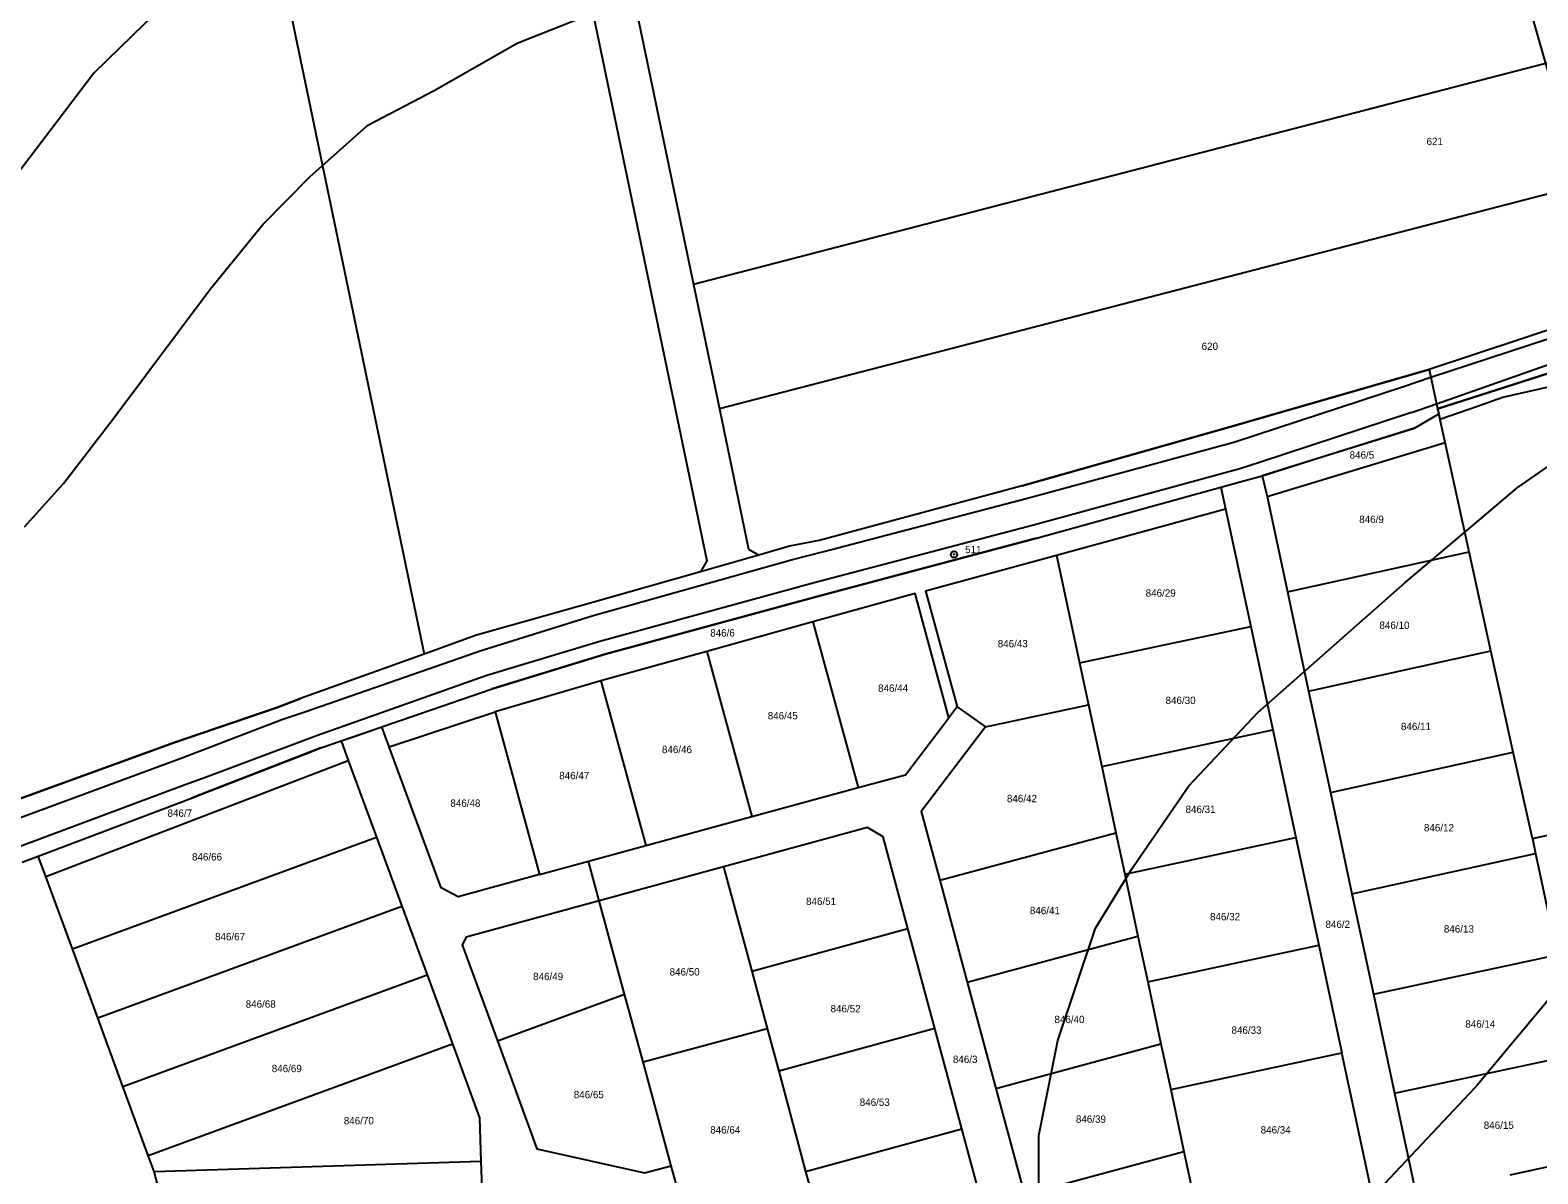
# Model space of a CAD drawing. Extents: x -725765 to -723182, y -1052705 to -1049154.
# Drawn here: x -725335 to -724986, y -1051345.9 to -1051081 of the extents above; entities that cross this region are included whole.
import ezdxf

# ---------------------------------------------------------------- set-up
doc = ezdxf.new("R2010")
doc.units = 0
for name, color, linetype in [('Vrstva 1', 7, 'Continuous'), ('Vrstva 12', 7, 'Continuous'), ('Vrstva 17', 7, 'Continuous'), ('Vrstva 18', 7, 'Continuous'), ('Vrstva 25', 7, 'Continuous'), ('Vrstva 4', 7, 'Continuous'), ('Vrstva 52', 7, 'Continuous')]:
    doc.layers.add(name, color=color, linetype=linetype)

msp = doc.modelspace()

# ---------------------------------------------------------------- linework, layer by layer
at = {"layer": 'Vrstva 1'}
for points in [[(-725237.59, -1050919.2), (-725178.34, -1051203.94)], [(-725299.6, -1050957.39), (-725243.81, -1051225.51)], [(-725199.88, -1051051.31), (-725181.44, -1051139.93)], [(-724957.95, -1051081.99), (-725181.44, -1051139.93)], [(-724945.68, -1051109.11), (-725175.46, -1051168.68)], [(-724936.98, -1051135.08), (-725011.19, -1051159.63)], [(-725181.44, -1051139.93), (-725175.46, -1051168.68)], [(-725057.43, -1051172.97), (-725011.19, -1051159.63)], [(-725011.19, -1051159.63), (-725010.8, -1051161.4)], [(-725009.19, -1051168.73), (-724973.59, -1051157.32)], [(-725010.8, -1051161.4), (-725009.44, -1051167.57)], [(-725175.46, -1051168.68), (-725168.7, -1051201.19)], [(-725014.58, -1051173.15), (-725008.93, -1051169.9)], [(-725009.44, -1051167.57), (-725009.19, -1051168.73)], [(-725009.19, -1051168.73), (-725008.93, -1051169.9)], [(-725007.48, -1051176.47), (-725008.93, -1051169.9)], [(-725105.34, -1051186.54), (-725057.43, -1051172.97)], [(-725014.58, -1051173.15), (-725049.8, -1051184.22)], [(-725048.67, -1051189.02), (-725007.48, -1051176.47)], [(-725001.9, -1051201.83), (-725007.48, -1051176.47)], [(-725054.07, -1051185.38), (-725049.8, -1051184.22)], [(-725049.8, -1051184.22), (-725048.67, -1051189.02)], [(-725105.34, -1051186.54), (-725152.07, -1051199.14)], [(-725102.07, -1051198.67), (-725059.35, -1051186.84)], [(-725059.35, -1051186.84), (-725054.07, -1051185.38)], [(-725059.35, -1051186.84), (-725058.28, -1051191.88)], [(-725048.67, -1051189.02), (-725043.95, -1051211.09)], [(-725097.41, -1051202.56), (-725058.28, -1051191.88)], [(-725058.28, -1051191.88), (-725052.47, -1051219.09)], [(-725168.7, -1051201.19), (-725166.37, -1051202.6)], [(-725159.2, -1051200.55), (-725166.37, -1051202.6)], [(-725152.07, -1051199.14), (-725159.2, -1051200.55)], [(-725102.07, -1051198.67), (-725152.54, -1051212.1)], [(-725043.95, -1051211.09), (-725001.9, -1051201.83)], [(-724996.84, -1051224.78), (-725001.9, -1051201.83)], [(-725166.37, -1051202.6), (-725179.86, -1051206.45)], [(-725178.34, -1051203.94), (-725179.86, -1051206.45)], [(-725127.77, -1051210.84), (-725097.41, -1051202.56)], [(-725097.41, -1051202.56), (-725092.08, -1051227.55)], [(-725179.86, -1051206.45), (-725205.38, -1051213.74)], [(-725152.54, -1051212.1), (-725201.88, -1051225.55)], [(-725122.34, -1051240.26), (-725130.18, -1051211.5), (-725153.8, -1051218.01)], [(-725127.77, -1051210.84), (-725120.44, -1051237.75)], [(-725043.95, -1051211.09), (-725039.05, -1051234.08)], [(-725205.38, -1051213.74), (-725231.72, -1051221.15)], [(-725153.8, -1051218.01), (-725178.36, -1051224.87)], [(-725153.8, -1051218.01), (-725143.33, -1051256.43)], [(-725092.08, -1051227.55), (-725052.47, -1051219.09)], [(-725052.47, -1051219.09), (-725047.35, -1051243.05)], [(-725231.72, -1051221.15), (-725243.81, -1051225.51)], [(-725243.81, -1051225.51), (-725272.4, -1051235.81)], [(-725201.88, -1051225.55), (-725228.08, -1051233.55)], [(-725178.36, -1051224.87), (-725202.93, -1051231.72)], [(-725178.36, -1051224.87), (-725167.93, -1051263.13)], [(-725039.05, -1051234.08), (-724996.84, -1051224.78)], [(-724991.68, -1051248.22), (-724996.84, -1051224.78)], [(-725092.08, -1051227.55), (-725090.01, -1051237.24)], [(-725202.93, -1051231.72), (-725227.4, -1051238.89)], [(-725202.93, -1051231.72), (-725192.53, -1051269.84)], [(-725277.83, -1051237.87), (-725272.4, -1051235.81)], [(-725253.58, -1051242.35), (-725228.08, -1051233.55)], [(-725039.05, -1051234.08), (-725034.03, -1051257.55)], [(-725301.81, -1051246.05), (-725277.83, -1051237.87)], [(-725251.89, -1051246.95), (-725227.4, -1051238.89)], [(-725227.4, -1051238.89), (-725217.14, -1051276.54)], [(-725143.33, -1051256.43), (-725132.36, -1051253.44), (-725122.34, -1051240.26)], [(-725120.44, -1051237.75), (-725122.34, -1051240.26)], [(-725120.44, -1051237.75), (-725113.87, -1051242.33)], [(-725113.87, -1051242.33), (-725090.01, -1051237.24)], [(-725090.01, -1051237.24), (-725086.96, -1051251.51)], [(-725263.03, -1051245.62), (-725253.58, -1051242.35)], [(-725251.89, -1051246.95), (-725253.58, -1051242.35)], [(-725113.87, -1051242.33), (-725128.77, -1051261.92), (-725124.47, -1051277.87)], [(-725086.96, -1051251.51), (-725047.35, -1051243.05)], [(-725047.35, -1051243.05), (-725042.03, -1051267.99)], [(-725340.64, -1051260.21), (-725301.81, -1051246.05)], [(-725267.7, -1051247.23), (-725293.37, -1051257.13)], [(-725267.7, -1051247.23), (-725263.03, -1051245.62)], [(-725263.03, -1051245.62), (-725261.37, -1051250.17)], [(-725217.14, -1051276.54), (-725235.96, -1051281.68), (-725239.88, -1051279.65), (-725251.89, -1051246.95)], [(-725331.42, -1051276.98), (-725261.37, -1051250.17)], [(-725261.37, -1051250.17), (-725254.86, -1051267.89)], [(-725034.03, -1051257.55), (-724991.68, -1051248.22)], [(-724987.27, -1051268.24), (-724991.68, -1051248.22)], [(-725086.96, -1051251.51), (-725083.68, -1051266.88)], [(-725293.37, -1051257.13), (-725297.69, -1051258.89)], [(-725167.93, -1051263.13), (-725143.33, -1051256.43)], [(-725034.03, -1051257.55), (-725029.02, -1051281.02)], [(-725333.14, -1051272.29), (-725297.69, -1051258.89)], [(-724987.27, -1051268.24), (-724951.45, -1051260.42)], [(-725192.53, -1051269.84), (-725167.93, -1051263.13)], [(-725325.25, -1051293.76), (-725254.86, -1051267.89)], [(-725254.86, -1051267.89), (-725248.99, -1051283.85)], [(-725131.81, -1051289.07), (-725137.54, -1051267.8), (-725141.21, -1051265.69), (-725174.5, -1051274.77)], [(-725124.47, -1051277.87), (-725083.68, -1051266.88)], [(-725083.68, -1051266.88), (-725081.64, -1051276.45)], [(-725081.64, -1051276.45), (-725042.03, -1051267.99)], [(-725042.03, -1051267.99), (-725036.7, -1051292.93)], [(-724987.27, -1051268.24), (-724986.54, -1051271.66)], [(-725205.74, -1051273.44), (-725192.53, -1051269.84)], [(-725029.02, -1051281.02), (-724986.54, -1051271.66)], [(-724986.54, -1051271.66), (-724981.52, -1051295.13)], [(-725336.9, -1051273.71), (-725333.14, -1051272.29)], [(-725331.42, -1051276.98), (-725333.14, -1051272.29)], [(-725217.14, -1051276.54), (-725205.74, -1051273.44)], [(-725203.26, -1051282.61), (-725205.74, -1051273.44)], [(-725174.5, -1051274.77), (-725203.26, -1051282.61)], [(-725174.5, -1051274.77), (-725167.99, -1051298.93)], [(-725325.25, -1051293.76), (-725331.42, -1051276.98)], [(-725124.47, -1051277.87), (-725118.1, -1051301.5)], [(-725081.64, -1051276.45), (-725078.56, -1051290.84)], [(-725029.02, -1051281.02), (-725024.07, -1051304.22)], [(-725319.39, -1051309.71), (-725248.99, -1051283.85)], [(-725248.99, -1051283.85), (-725243.13, -1051299.81)], [(-725203.26, -1051282.61), (-725234.11, -1051291.09), (-725235.04, -1051292.84), (-725226.86, -1051315.09)], [(-725197.4, -1051304.23), (-725203.26, -1051282.61)], [(-725167.99, -1051298.93), (-725131.81, -1051289.07)], [(-725125.56, -1051312.24), (-725131.81, -1051289.07)], [(-725118.1, -1051301.5), (-725078.56, -1051290.84)], [(-725078.56, -1051290.84), (-725076.31, -1051301.39)], [(-725319.39, -1051309.71), (-725325.25, -1051293.76)], [(-725076.31, -1051301.39), (-725036.7, -1051292.93)], [(-725036.7, -1051292.93), (-725031.38, -1051317.87)], [(-725024.07, -1051304.22), (-724981.52, -1051295.13)], [(-725167.99, -1051298.93), (-725164.41, -1051312.2)], [(-725313.53, -1051325.67), (-725243.13, -1051299.81)], [(-725243.13, -1051299.81), (-725237.27, -1051315.76)], [(-725118.1, -1051301.5), (-725111.48, -1051326.08)], [(-725076.31, -1051301.39), (-725073.24, -1051315.78)], [(-725226.86, -1051315.09), (-725197.4, -1051304.23)], [(-725193.14, -1051319.94), (-725197.4, -1051304.23)], [(-725024.07, -1051304.22), (-725019.16, -1051327.2)], [(-725313.53, -1051325.67), (-725319.39, -1051309.71)], [(-725193.14, -1051319.94), (-725164.41, -1051312.2)], [(-725164.41, -1051312.2), (-725161.74, -1051322.1)], [(-725125.56, -1051312.24), (-725161.74, -1051322.1)], [(-725119.32, -1051335.41), (-725125.56, -1051312.24)], [(-725307.67, -1051341.63), (-725237.27, -1051315.76)], [(-725237.27, -1051315.76), (-725230.97, -1051332.9), (-725230.66, -1051342.93)], [(-725226.86, -1051315.09), (-725217.69, -1051340.06), (-725192.78, -1051345.66), (-725186.63, -1051343.99)], [(-725111.48, -1051326.08), (-725073.24, -1051315.78)], [(-725073.24, -1051315.78), (-725070.99, -1051326.32)], [(-725186.63, -1051343.99), (-725193.14, -1051319.94)], [(-725070.99, -1051326.32), (-725031.38, -1051317.87)], [(-725029.24, -1051356.22), (-725024.76, -1051348.89), (-725031.38, -1051317.87)], [(-725019.16, -1051327.2), (-724976.54, -1051318.1)], [(-725161.74, -1051322.1), (-725155.5, -1051345.28)], [(-725307.67, -1051341.63), (-725313.53, -1051325.67)], [(-725111.48, -1051326.08), (-725104.85, -1051350.67)], [(-725070.99, -1051326.32), (-725067.91, -1051340.72)], [(-725019.16, -1051327.2), (-725014.14, -1051350.7)], [(-725155.5, -1051345.28), (-725119.32, -1051335.41)], [(-725113.07, -1051358.59), (-725119.32, -1051335.41)], [(-725104.85, -1051350.67), (-725067.91, -1051340.72)], [(-725067.91, -1051340.72), (-725065.39, -1051352.53)], [(-724992.44, -1051346.06), (-724971.42, -1051341.57)], [(-725306.31, -1051345.31), (-725307.67, -1051341.63)], [(-725306.31, -1051345.31), (-725230.66, -1051342.93)], [(-725230.66, -1051342.93), (-725230.25, -1051355.84), (-725232.32, -1051365.04)], [(-725185.11, -1051349.59), (-725186.63, -1051343.99)], [(-725305.49, -1051348.58), (-725306.31, -1051345.31)], [(-725155.5, -1051345.28), (-725154.28, -1051349.81)]]:
    msp.add_lwpolyline(points, dxfattribs=at)
at = {"layer": 'Vrstva 12'}
msp.add_lwpolyline([(-724973.47, -1051126.02), (-724988.81, -1051072.44)], dxfattribs=at)
at = {"layer": 'Vrstva 25'}
for radius in [0.75, 0.032]:
    msp.add_circle((-725121.15, -1051202.42), radius, dxfattribs=at)
at = {"layer": 'Vrstva 4'}
for points in [[(-725010.8, -1051161.4), (-724979.2, -1051151.01)], [(-725009.44, -1051167.57), (-724976.7, -1051156.09)], [(-725056.39, -1051176.43), (-725017.09, -1051163.52)], [(-725017.09, -1051163.52), (-725010.8, -1051161.4)], [(-725015.24, -1051169.54), (-725050.19, -1051181.06)], [(-725015.24, -1051169.54), (-725009.44, -1051167.57)], [(-725104.44, -1051189.5), (-725056.39, -1051176.43)], [(-725050.19, -1051181.06), (-725054.96, -1051182.59)], [(-725054.96, -1051182.59), (-725102.74, -1051195.68)], [(-725151.28, -1051201.72), (-725104.44, -1051189.5)], [(-725102.74, -1051195.68), (-725153.55, -1051209.03)], [(-725158.56, -1051203.58), (-725151.28, -1051201.72)], [(-725204.7, -1051216.55), (-725158.56, -1051203.58)], [(-725153.55, -1051209.03), (-725203.14, -1051222.59)], [(-725230.65, -1051224.71), (-725204.7, -1051216.55)], [(-725203.14, -1051222.59), (-725229.31, -1051230.45)], [(-725271.2, -1051238.78), (-725230.65, -1051224.71)], [(-725229.31, -1051230.45), (-725268.51, -1051244.33)], [(-725276.77, -1051240.65), (-725271.2, -1051238.78)], [(-725299.71, -1051249.48), (-725276.77, -1051240.65)], [(-725268.51, -1051244.33), (-725294.41, -1051254.07)], [(-725339.56, -1051264.16), (-725299.71, -1051249.48)], [(-725294.41, -1051254.07), (-725299.16, -1051255.8)], [(-725299.16, -1051255.8), (-725338.17, -1051270.34)]]:
    msp.add_lwpolyline(points, dxfattribs=at)
at = {"layer": 'Vrstva 52'}
for points in [[(-725299.81, -1051071), (-725320.31, -1051091), (-725343.88, -1051122)], [(-725336.31, -1051196), (-725327.31, -1051186), (-725315.81, -1051171), (-725293.31, -1051141), (-725281.19, -1051126), (-725270.31, -1051115), (-725256.88, -1051103), (-725241.5, -1051095), (-725222.31, -1051084), (-725204.74, -1051077.08)], [(-724711.14, -1051080.07), (-724811.24, -1051105.56), (-724810.03, -1051107.31), (-724816.84, -1051108.91), (-724856.27, -1051116.41), (-724925.34, -1051132.13), (-724935.23, -1051134.64), (-724936.98, -1051135.08), (-725011.19, -1051159.63), (-725057.43, -1051172.97), (-725105.34, -1051186.54), (-725152.07, -1051199.14), (-725159.2, -1051200.55), (-725166.37, -1051202.6), (-725179.86, -1051206.45), (-725205.38, -1051213.74), (-725231.72, -1051221.15), (-725243.81, -1051225.51), (-725272.4, -1051235.81), (-725277.83, -1051237.87), (-725301.81, -1051246.05), (-725340.64, -1051260.21)], [(-724738.66, -1051101.7), (-724743.22, -1051102.61), (-724765.92, -1051107.34), (-724788.6, -1051112.06), (-724811.15, -1051116.69), (-724834.36, -1051120.96), (-724845.44, -1051123.38), (-724860.72, -1051126.71), (-724884.18, -1051130.69), (-724904.47, -1051135.61), (-724926.75, -1051141.34), (-724930.97, -1051142.63), (-724948.22, -1051147.9), (-724958.02, -1051151.55), (-724968.47, -1051155.44), (-724973.12, -1051157.17), (-724973.59, -1051157.32), (-725009.19, -1051168.73), (-725008.93, -1051169.9)], [(-725008.93, -1051169.9), (-725008.66, -1051171.13), (-725000, -1051168.07), (-724994.13, -1051166), (-724972.25, -1051161.09), (-724967.44, -1051160), (-724949.63, -1051156), (-724944.63, -1051155)], [(-725336.9, -1051273.71), (-725333.14, -1051272.29), (-725297.69, -1051258.89), (-725293.37, -1051257.13), (-725270.8, -1051248.42), (-725267.7, -1051247.23), (-725263.03, -1051245.62), (-725259.76, -1051244.49), (-725253.58, -1051242.35), (-725228.08, -1051233.55), (-725201.88, -1051225.55), (-725152.54, -1051212.1), (-725102.07, -1051198.67), (-725059.35, -1051186.84), (-725054.07, -1051185.38), (-725049.8, -1051184.22), (-725035.45, -1051179.71), (-725014.58, -1051173.15), (-725008.93, -1051169.9)], [(-724980.17, -1051301.45), (-725000, -1051325.25), (-725000.63, -1051326), (-725025.13, -1051352), (-725041.13, -1051363), (-725055.63, -1051369), (-725081.63, -1051375), (-725091.38, -1051374), (-725097.88, -1051366), (-725101.5, -1051353), (-725101.5, -1051337), (-725097.13, -1051315), (-725088.38, -1051289), (-725079.81, -1051275), (-725066.81, -1051256), (-725050.81, -1051239), (-725016.81, -1051209), (-725002.91, -1051197.24), (-725000, -1051194.77), (-724990.81, -1051187), (-724969.75, -1051172.41)]]:
    msp.add_lwpolyline(points, dxfattribs=at)

# ---------------------------------------------------------------- texts
at = {"layer": 'Vrstva 17'}
msp.add_text('511 ', height=1.7, dxfattribs=at).set_placement((-725118.58, -1051202.15))
at = {"layer": 'Vrstva 18'}
for s, p in [('621', (-725011.76, -1051107.65)), ('620', (-725063.83, -1051155.07)), ('846/5', (-725029.57, -1051180.24)), ('846/9', (-725027.35, -1051195.16)), ('846/29', (-725076.78, -1051212.21)), ('846/10', (-725022.66, -1051219.67)), ('846/6', (-725177.57, -1051221.44)), ('846/43', (-725111.03, -1051223.93)), ('846/44', (-725138.72, -1051234.23)), ('846/30', (-725072.17, -1051237.07)), ('846/45', (-725164.27, -1051240.62)), ('846/11', (-725017.69, -1051243.11)), ('846/46', (-725188.76, -1051248.44)), ('846/47', (-725212.54, -1051254.47)), ('846/48', (-725237.74, -1051260.87)), ('846/42', (-725108.9, -1051259.8)), ('846/31', (-725067.55, -1051262.29)), ('846/7', (-725303.22, -1051263.18)), ('846/12', (-725012.36, -1051266.55)), ('846/66', (-725297.55, -1051273.3)), ('846/51', (-725155.4, -1051283.6)), ('846/41', (-725103.58, -1051285.73)), ('846/32', (-725061.88, -1051287.15)), ('846/2', (-725035.16, -1051288.92)), ('846/13', (-725007.75, -1051289.99)), ('846/67', (-725292.22, -1051291.77)), ('846/49', (-725218.58, -1051301)), ('846/50', (-725186.99, -1051299.93)), ('846/68', (-725285.12, -1051307.39)), ('846/52', (-725149.72, -1051308.46)), ('846/40', (-725097.9, -1051310.95)), ('846/33', (-725056.91, -1051313.43)), ('846/14', (-725002.78, -1051312.01)), ('846/69', (-725279.09, -1051322.31)), ('846/3', (-725121.41, -1051320.18)), ('846/65', (-725209.17, -1051328.35)), ('846/53', (-725142.98, -1051330.12)), ('846/70', (-725262.41, -1051334.39)), ('846/39', (-725092.93, -1051334.03)), ('846/15', (-724998.52, -1051335.45)), ('846/64', (-725177.58, -1051336.52)), ('846/34', (-725050.16, -1051336.52))]:
    msp.add_text(s, height=1.7, dxfattribs=at).set_placement(p)

doc.saveas('drawing.dxf')
